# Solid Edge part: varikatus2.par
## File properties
Author: Mac
Template: Normal.par
Last saved by: Mac
Revision: 11
Application: Solid Edge
Material: Epoxy, cast rigid
Face Style: White
Fill Style: ANSI34(Plastic)
Virtual Style: Shiny resin yellow
Coef. of Thermal Exp: 5.9e-05
Thermal Conductivity: 2.1
Specific Heat: 0.0
Modulus of Elasticity: 3102640650.0
Poission's Ratio: 0.37
Yield Stress: 65500191.5
Ultimate Stress: 0.0
Elongation: 0.0
Density: 1300,000 kg/m^3
Accuracy: 0,990
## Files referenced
..\..\paat abi3\Asm12.asm
BC:\Documents and Settings\Mac\Desktop\paat\Abi\paat abi3\Asm12.asm
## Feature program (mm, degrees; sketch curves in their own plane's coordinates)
make body feature "unnamed MakeBodyFeature 1"
sketch for "unnamed Cutout 1" plane through (0, 0, 0) normal (0, -1, 0) x-axis (1, 0, 0)
  line (0, 5.6155) -> (0, -11.724)
  line (0, -11.724) -> (0, -14.0241)
  line (0, -14.0241) -> (6.1073, -14.0241)
  line (6.1073, -14.0241) -> (6.1073, 5.6155)
  line (6.1073, 5.6155) -> (0, 5.6155)
extrude "unnamed Cutout 1" cut through along -normal
sketch for "unnamed Cutout 2" plane through (-15.7899, 12.8147, 0.0021) normal (0, 0, -1) x-axis (1, 0, 0)
  bspline degree 3 poles (-16.3432, 14.2922) (-16.3048, 11.4613) (-16.2676, 8.6305) (-16.2181, 5.8) (-16.1773, 3.4617) (-16.1292, 1.1235) (-16.0285, -2.3826) (-15.9901, -3.551) (-15.9187, -5.3029) (-15.893, -5.8868) (-15.8332, -7.054) (-15.7991, -7.6373) (-15.7255, -8.6941) (-15.6889, -9.1678) (-15.6282, -9.7583) (-15.6153, -9.8764) (-15.5878, -10.1122) (-15.573, -10.2299) (-15.5546, -10.362) (-15.5526, -10.3767) (-15.5484, -10.406) (-15.5463, -10.4207) (-15.5399, -10.4648) (-15.5356, -10.4941) (-15.5223, -10.5821) (-15.5128, -10.6404) (-15.4971, -10.7274) (-15.4915, -10.7563) (-15.4827, -10.7995) (-15.4796, -10.8138) (-15.4734, -10.8424) (-15.4702, -10.8566) (-15.4601, -10.8991) (-15.4528, -10.9272) (-15.4408, -10.9689) (-15.4366, -10.9827) (-15.4278, -11.0101) (-15.4232, -11.0238) (-15.4114, -11.0571) (-15.4038, -11.0767) (-15.3874, -11.1155) (-15.3787, -11.1347) (-15.3602, -11.1723) (-15.3503, -11.1907) (-15.3295, -11.2266) (-15.3185, -11.2441) (-15.2604, -11.3294) (-15.2036, -11.3916) (-15.1095, -11.4759) (-15.0767, -11.5026) (-15.026, -11.5403) (-15.0088, -11.5526) (-14.974, -11.5766) (-14.9563, -11.5883) (-14.8671, -11.6456) (-14.7924, -11.6872) (-14.6779, -11.7449) (-14.6393, -11.7633) (-14.5617, -11.7988) (-14.5227, -11.8159) (-14.4049, -11.8651) (-14.3254, -11.8955) (-14.0851, -11.9815) (-13.9225, -12.0318) (-13.5938, -12.1228) (-13.4276, -12.1637) (-13.0939, -12.2392) (-12.9262, -12.2736) (-12.4216, -12.3688) (-12.0831, -12.4214) (-11.4603, -12.5073) (-11.1752, -12.542) (-10.6045, -12.6044) (-10.3188, -12.632) (-9.4611, -12.7072) (-8.8885, -12.7467) (-7.1689, -12.844) (-6.0205, -12.881) (-2.5718, -12.945) (-0.273, -12.9257) (4.3226, -12.8276) (6.6195, -12.7467) (10.0634, -12.5935) (11.2112, -12.537) (12.6458, -12.4601) (12.9327, -12.4445) (13.3631, -12.4205) (13.5065, -12.4124) (13.7217, -12.4002) (13.7934, -12.3962) (13.9369, -12.3879) (14.0086, -12.3838) (14.152, -12.3756) (14.2237, -12.3714) (14.3672, -12.363) (14.439, -12.3588) (14.6544, -12.346) (14.7982, -12.3374) (15.2243, -12.312) (15.507, -12.2952) (15.7899, -12.2788) knots 0 0.2276 0.338 0.3932 0.4208 0.4484 0.4708 0.4764 0.482 0.4827 0.4834 0.4848 0.4876 0.489 0.4897 0.4904 0.4918 0.4925 0.4932 0.4942 0.4953 0.4963 0.4973 0.5014 0.5035 0.5045 0.5055 0.5096 0.5117 0.5137 0.5178 0.526 0.5342 0.5424 0.5588 0.5726 0.5864 0.6139 0.6691 0.7795 0.8899 0.9451 0.9589 0.9658 0.9692 0.9727 0.9761 0.9796 0.9865 1 multiplicities 4 3 2 2 2 2 2 2 2 2 2 2 2 2 2 2 2 2 2 2 2 2 2 2 2 2 2 2 2 2 2 2 2 2 2 2 2 2 2 2 2 2 2 2 2 2 2 2 2 4
  line (15.7899, -12.2788) -> (15.7899, 14.2922)
  line (-16.3432, 14.2922) -> (15.7899, 14.2922)
extrude "unnamed Cutout 2" cut through along +normal
sketch for "ExtrudedProtrusion_3" plane through (0, 0, 0.0021) normal (0, 0, 1) x-axis (1, 0, 0)
  line (0, 24.9054) -> (0, 0.1618)
  line (-31.9352, 0.1618) -> (0, 0.1618)
  bspline degree 3 poles (-31.9352, 0.1618) (-31.9042, 2.4453) (-31.8722, 4.7285) (-31.8323, 7.0115) (-31.7915, 9.3493) (-31.7434, 11.6869) (-31.6428, 15.1914) (-31.6045, 16.359) (-31.5331, 18.1096) (-31.5074, 18.6929) (-31.4477, 19.8583) (-31.4137, 20.4404) (-31.3402, 21.4949) (-31.3037, 21.9666) (-31.2434, 22.5532) (-31.2307, 22.6705) (-31.2033, 22.9042) (-31.1887, 23.0206) (-31.1706, 23.1508) (-31.1686, 23.1653) (-31.1645, 23.1942) (-31.1624, 23.2089) (-31.1561, 23.2526) (-31.1518, 23.2815) (-31.1387, 23.3677) (-31.1296, 23.4243) (-31.1145, 23.5076) (-31.1092, 23.5351) (-31.1008, 23.576) (-31.098, 23.5896) (-31.0921, 23.6165) (-31.0891, 23.6295) (-31.0799, 23.6684) (-31.0734, 23.6936) (-31.0628, 23.7303) (-31.0591, 23.7424) (-31.0515, 23.7662) (-31.0475, 23.778) (-31.0375, 23.8062) (-31.0312, 23.8225) (-31.0177, 23.8546) (-31.0105, 23.8703) (-30.9954, 23.9009) (-30.9875, 23.9157) (-30.971, 23.9441) (-30.9626, 23.9575) (-30.917, 24.0244) (-30.8706, 24.0757) (-30.7904, 24.1476) (-30.7619, 24.1707) (-30.7174, 24.2038) (-30.7019, 24.2149) (-30.6706, 24.2365) (-30.6547, 24.2471) (-30.5737, 24.2991) (-30.5047, 24.3376) (-30.3971, 24.3918) (-30.3605, 24.4093) (-30.287, 24.4429) (-30.2498, 24.4591) (-30.1373, 24.5062) (-30.0609, 24.5354) (-29.8283, 24.6186) (-29.6702, 24.6676) (-29.3488, 24.7566) (-29.1853, 24.7968) (-28.8565, 24.8712) (-28.6911, 24.9052) (-28.1926, 24.9992) (-27.8572, 25.0513) (-27.2387, 25.1366) (-26.9556, 25.1711) (-26.3881, 25.2332) (-26.1038, 25.2607) (-25.2498, 25.3355) (-24.6794, 25.3749) (-22.965, 25.4719) (-21.8192, 25.5088) (-18.3764, 25.5727) (-16.0804, 25.5535) (-11.4884, 25.4554) (-9.1928, 25.3745) (-5.7501, 25.2214) (-4.6026, 25.1649) (-3.1683, 25.0881) (-2.8815, 25.0724) (-2.4512, 25.0485) (-2.3078, 25.0404) (-2.0926, 25.0282) (-2.0209, 25.0241) (-1.8775, 25.0159) (-1.8057, 25.0118) (-1.6623, 25.0035) (-1.5907, 24.9993) (-1.4473, 24.991) (-1.3756, 24.9867) (-1.1604, 24.974) (-1.017, 24.9655) (-0.8735, 24.9569) (-0.5823, 24.9395) (-0.2911, 24.9222) (0, 24.9054) knots 0 0.2113 0.322 0.3774 0.405 0.4327 0.4552 0.4608 0.4664 0.4671 0.4678 0.4692 0.4721 0.4735 0.4742 0.4749 0.4763 0.477 0.4777 0.4787 0.4797 0.4808 0.4818 0.4859 0.4879 0.489 0.49 0.4941 0.4962 0.4982 0.5023 0.5105 0.5187 0.527 0.5434 0.5572 0.5711 0.5987 0.6541 0.7648 0.8755 0.9308 0.9446 0.9516 0.955 0.9585 0.9619 0.9654 0.9723 1 multiplicities 4 3 2 2 2 2 2 2 2 2 2 2 2 2 2 2 2 2 2 2 2 2 2 2 2 2 2 2 2 2 2 2 2 2 2 2 2 2 2 2 2 2 2 2 2 2 2 2 3 4
extrude "ExtrudedProtrusion_3" add finite 0.2 along +normal
sketch for "unnamed Cutout 3" plane through (22.4735, -49.0285, -23.78) normal (0, -1, 0) x-axis (1, 0, 0)
extrude "unnamed Cutout 3" cut through along -normal
sketch for "unnamed Cutout 4" plane through (0, 0, 0) normal (0, 0, 1) x-axis (1, 0, 0)
  line (57.8061, 0.1618) -> (-51.958, 0.1618)
extrude "unnamed Cutout 4" cut finite 69.2541 symmetric
body pattern "unnamed BodyPattern 1"
pattern "unnamed Pattern 1"
sketch for "unnamed Cutout 5" plane through (-15.9676, 0.1618, 0.0021) normal (0, 0, -1) x-axis (0, -1, 0)
extrude "unnamed Cutout 5" cut through along -normal
Other named dimensions: "ExtrudedSurface_3": FiniteDepth = 33.6443 mm
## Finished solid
Body 1: solid body, 39 faces, 106 edges, 69 vertices.
  Faces by surface: spline 18, plane 12, swept 5, cylinder 4
  Edges by curve: intersection 45, line 29, spline 24, circle 8
Body 2: solid body, 12 faces, 30 edges, 20 vertices.
  Faces by surface: spline 10, plane 2
  Edges by curve: spline 11, line 10, curve on surface 5, circle 2, ellipse 2
Body 3: sheet body, 1 face, 4 edges, 4 vertices.
  Faces by surface: swept 1
  Edges by curve: line 2, spline 2
Body 4: sheet body, 3 faces, 10 edges, 8 vertices.
  Faces by surface: plane 2, swept 1
  Edges by curve: line 8, spline 2
Bounding box of the edges (mm; curved faces can reach further): 91.395 x 62.530 x 33.644, from (-42.5425, -28.123, -16.8222) to (48.8526, 34.4074, 16.8222).
Cylindrical faces by radius (mm): R0.2 x4
Planar faces by outward normal: +x 2, +y 1, +z 4, -x 1, -y 1, -z 1, oblique 4
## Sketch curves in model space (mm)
line (-17.5476, 25.3492, -0.1249) -> (-17.5476, 25.3492, 0.2021)
line (-17.5476, 27.7753, -0.1249) -> (-17.5476, 25.3492, -0.1249)
line (-17.5476, 27.7753, 1.4256) -> (-17.5476, 27.7753, -0.1249)
arc centre (-17.5476, 25.7809, 1.2553) radius 2.0016 from (-17.5476, 27.7753, 1.4256) through (-17.5476, 27.0895, 2.77) to (-17.5476, 25.7788, 3.257)
line (-17.5476, 25.7788, 3.257) -> (-17.5476, 25.5529, 3.2567)
line (-17.5476, 25.5529, 3.2567) -> (-17.5476, 25.3492, 0.2021)
line (-28.1084, 25.0097, 2.5413) -> (-28.1084, 25.2411, 2.5413)
spline (-28.1084, 25.2411, 2.5413) -> (-28.1084, 26.6013, 2.0173) -> (-28.1084, 27.2404, 0.71)
line (-28.1084, 27.2404, -0.5005) -> (-28.1084, 27.2404, 0.71)
line (-28.1084, 24.8257, -0.5005) -> (-28.1084, 27.2404, -0.5005)
line (-28.1084, 24.8257, 0.2021) -> (-28.1084, 24.8257, -0.5005)
spline (-28.1084, 24.8257, 0.2021) -> (-28.1084, 24.9178, 1.3717) -> (-28.1084, 25.0097, 2.5413)
line (0.0185, 25.1301, 4.3729) -> (0.0163, 25.0926, 4.3727)
spline (0.0163, 25.0926, 4.3727) -> (0.2172, 24.9389, 2.1168) -> (0.4024, 24.798, 0.0374)
line (0.4024, 24.798, 0.0374) -> (0.3909, 24.5967, 0.0363)
line (0.3909, 24.5967, 0.0363) -> (-0.0129, 24.9061, 4.5709)
line (0.0001, 25.1337, 4.5721) -> (-0.0129, 24.9061, 4.5709)
arc centre (0.1852, 25.1342, 2.5817) radius 1.999 from (0.2831, 27.1225, 2.7627) through (0.1199, 26.4391, 4.0945) to (0.0001, 25.1337, 4.5721)
spline (0.2831, 27.1225, 2.7627) -> (0.9818, 27.6913, -4.3994) -> (1.6766, 28.1816, -11.5681)
line (1.6766, 28.1816, -11.5681) -> (1.6652, 27.9818, -11.5692)
spline (1.6652, 27.9818, -11.5692) -> (1.1461, 27.6223, -6.2093) -> (0.2733, 26.9236, 2.7446)
ellipse centre (0.1853, 25.1205, 2.5728) radii 1.8156, 1.8048 from (0.2733, 26.9236, 2.7446) through (0.1264, 26.3083, 3.9434) to (0.0185, 25.1301, 4.3729)
spline (0, 25.1312, 0) -> (-29.743, 24.879, 0) -> (-32.1624, 0, 0)
line (-32.1207, 23.1926, 0) -> (-32.1207, 0.1618, 0)
arc centre (-30.1207, 23.1926, 0) radius 2 from (-30.1759, 25.1918, 0) through (-31.5543, 24.5872, 0) to (-32.1207, 23.1926, 0)
spline (-9.68, 25.5807, 0) -> (-21.5081, 25.7087, 0) -> (-30.1759, 25.1918, 0)
line (0, 25.1312, 0) -> (-9.68, 25.5807, 0)
arc centre (0, 25.1312, 2.5556) radius 1.8156 from (0, 26.9394, 2.7192) through (0, 26.3156, 3.9317) to (0, 25.1312, 4.3712)
line (0, 25.1312, 4.3712) -> (0, 25.0936, 4.3712)
spline (0, 25.0936, 4.3712) -> (0, 24.957, 2.1856) -> (0, 24.8212, 0)
line (0, 24.8212, 0) -> (0, 0.1618, 0)
line (0, -1.9856, 0) -> (0, 0.1618, 0)
line (0, -1.9856, 7.6981) -> (0, -1.9856, 0)
line (0, 30.3254, 7.6981) -> (0, -1.9856, 7.6981)
line (0, 30.3254, -11.7381) -> (0, 30.3254, 7.6981)
line (0, 28.0789, -11.7381) -> (0, 30.3254, -11.7381)
spline (0, 28.0789, -11.7381) -> (0, 27.5485, -4.5064) -> (0, 26.9394, 2.7192)
line (-9.6516, 27.9224, -8.3811) -> (-9.6516, 32.8266, -8.3811)
line (-9.6516, 32.8266, -8.3811) -> (-9.6516, 32.8266, 7.404)
line (-9.6516, 32.8266, 7.404) -> (-9.6516, -3.8209, 7.404)
line (-9.6516, -3.8209, 7.404) -> (-9.6516, -3.8209, 0)
line (-9.6516, -3.8209, 0) -> (-9.6516, 0.1618, 0)
line (-9.6516, 25.2703, 0) -> (-9.6516, 0.1618, 0)
line (-9.6516, 25.2703, 0) -> (-9.6516, 25.4991, 3.6601)
line (-9.6516, 25.5794, 3.6601) -> (-9.6516, 25.4991, 3.6601)
arc centre (-9.6516, 25.5794, 1.8495) radius 1.8106 from (-9.6516, 25.5794, 3.6601) through (-9.6516, 26.8261, 3.1624) to (-9.6516, 27.3876, 1.9431)
line (-9.6516, 27.3876, 1.9431) -> (-9.6516, 27.9224, -8.3811)
spline (16.2077, -49.0285, -20.3493) -> (-6.1466, -49.0285, -9.4951) -> (-40.805, -49.0285, -1.2863)
spline (33.7647, -49.0285, -6.8931) -> (14.1769, -49.0285, -7.8093) -> (0.0044, -49.0285, -11.7257)
line (52.3137, -49.0285, -6.8931) -> (33.7647, -49.0285, -6.8931)
line (-13.2629, -49.0285, -20.3493) -> (-11.8368, -49.0285, -7.7341)
line (73.4091, -49.0285, -20.3493) -> (-13.2629, -49.0285, -20.3493)
line (73.4091, -49.0285, -20.3493) -> (52.3137, -49.0285, -6.8931)
line (-37.1541, 0.1618, 2.1041) -> (-37.1541, 0.1618, 18.0368)
line (-37.1541, 0.1618, 18.0368) -> (48.8526, 0.1618, 18.0368)
line (48.8526, 0.1618, 18.0368) -> (48.8526, 0.1618, 8.0668)
spline (48.8526, 0.1618, 8.0668) -> (5.7708, 0.1618, 6.1421) -> (-37.1541, 0.1618, 2.1041)
line (-42.5425, 0, -1.6706) -> (-38.1207, 0, 2.053)
line (-37.1541, 0, 2.1041) -> (-38.1207, 0, 2.053)
spline (48.8526, 0, 8.0668) -> (5.7708, 0, 6.1421) -> (-37.1541, 0, 2.1041)
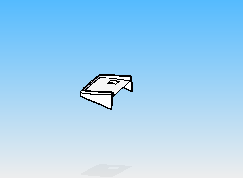
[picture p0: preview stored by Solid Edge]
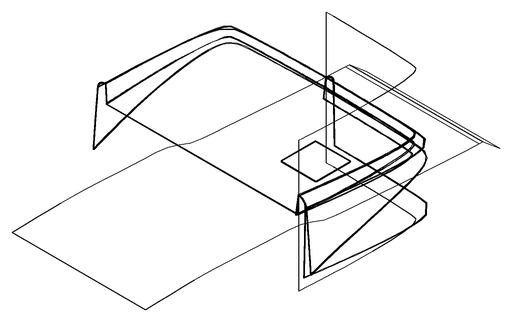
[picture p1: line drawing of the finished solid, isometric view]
